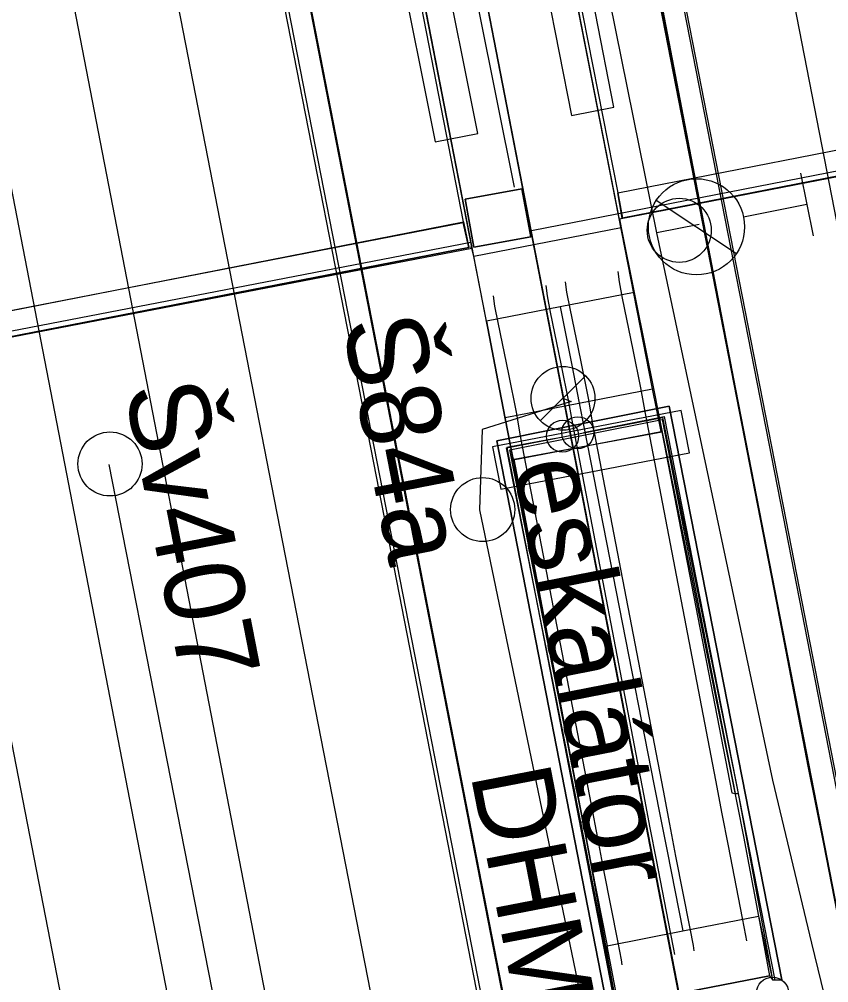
# Model space of a CAD drawing. Extents: x -545736 to -544888, y -1122892 to -1119128.
# Drawn here: x -545200.03 to -545187.41, y -1121808.48 to -1121793.44 of the extents above; entities that cross this region are included whole.
import ezdxf

# ---------------------------------------------------------------- set-up
doc = ezdxf.new("R2010")
doc.units = 0
for name, color, linetype in [('Podbarveni_Nastupiste', 7, 'Continuous'), ('Podbarveni_Zastreseni_Pozemni', 7, 'Continuous'), ('Vrstva 1 - Koleje', 7, 'Continuous'), ('Vrstva 13', 7, 'Continuous'), ('Vrstva 14_zastreseni a nastupiste', 7, 'Continuous'), ('Vrstva 16_plochy', 7, 'Continuous'), ('Vrstva 17_ploty - zabradli', 7, 'Continuous'), ('Vrstva 18_mosty', 7, 'Continuous'), ('Vrstva 23 - PHS - pozemni - schody - eskalatory', 7, 'Continuous'), ('Vrstva 29 - sdelzar', 7, 'Continuous'), ('Vrstva 30', 7, 'Continuous'), ('Vrstva 31', 7, 'Continuous'), ('Vrstva 33 - prvky sdelzar', 7, 'Continuous'), ('Vrstva 35', 7, 'Continuous'), ('Vrstva 4 - Teren - stezky - prechody - plochy', 7, 'Continuous'), ('Vrstva 41', 7, 'Continuous'), ('Vrstva 42', 7, 'Continuous'), ('Vrstva 43', 7, 'Continuous'), ('Vrstva 44', 7, 'Continuous'), ('Vrstva 47', 7, 'Continuous'), ('Vrstva 63', 7, 'Continuous')]:
    doc.layers.add(name, color=color, linetype=linetype)

msp = doc.modelspace()

# ---------------------------------------------------------------- linework, layer by layer
at = {"layer": 'Podbarveni_Nastupiste'}
for points in [[(-545217.368, -1121682.822), (-545215.446, -1121692.657), (-545213.545, -1121702.425), (-545211.641, -1121712.196), (-545209.721, -1121722.039), (-545207.816, -1121731.8), (-545205.906, -1121741.605), (-545203.994, -1121751.399), (-545202.093, -1121761.155), (-545200.179, -1121770.948), (-545198.277, -1121780.734), (-545196.359, -1121790.595), (-545195.979, -1121792.554), (-545194.455, -1121800.349), (-545192.535, -1121810.197), (-545190.626, -1121819.979), (-545188.728, -1121829.75), (-545186.804, -1121839.582), (-545184.9, -1121849.369), (-545182.993, -1121859.16)], [(-545176.664, -1121859.989), (-545178.574, -1121850.184), (-545180.481, -1121840.388), (-545182.39, -1121830.601), (-545184.299, -1121820.832), (-545186.202, -1121811.019), (-545188.114, -1121801.21), (-545190.028, -1121791.416), (-545191.936, -1121781.597), (-545194.23, -1121769.859), (-545195.758, -1121762.016), (-545197.67, -1121752.211), (-545199.585, -1121742.389), (-545201.492, -1121732.62), (-545203.329, -1121723.177), (-545205.298, -1121713.047), (-545207.216, -1121703.229), (-545209.127, -1121693.444), (-545211.033, -1121683.652)]]:
    msp.add_lwpolyline(points, dxfattribs=at)
at = {"layer": 'Podbarveni_Zastreseni_Pozemni'}
for points in [[(-545158.353, -1121955.704), (-545167.91, -1121906.688), (-545177.482, -1121857.6), (-545187.03, -1121808.63), (-545196.619, -1121759.457), (-545206.211, -1121710.262)], [(-545201.855, -1121760.601), (-545192.303, -1121809.6), (-545182.738, -1121858.66), (-545173.147, -1121907.858), (-545163.62, -1121956.724)]]:
    msp.add_lwpolyline(points, dxfattribs=at)
at = {"layer": 'Vrstva 1 - Koleje'}
for points in [[(-545219.01, -1121683.169), (-545217.101, -1121692.961), (-545215.17, -1121702.86), (-545213.27, -1121712.617), (-545211.361, -1121722.411), (-545209.465, -1121732.134), (-545207.557, -1121741.929), (-545205.641, -1121751.761), (-545203.736, -1121761.535), (-545201.841, -1121771.262), (-545199.933, -1121781.054), (-545197.636, -1121792.838), (-545196.098, -1121800.727), (-545194.176, -1121810.583), (-545192.282, -1121820.3), (-545190.374, -1121830.083), (-545188.448, -1121839.971), (-545186.548, -1121849.715), (-545184.635, -1121859.52)], [(-545209.393, -1121683.199), (-545207.488, -1121692.987), (-545205.563, -1121702.847), (-545203.658, -1121712.62), (-545201.742, -1121722.443), (-545199.842, -1121732.176), (-545197.931, -1121741.977), (-545196.019, -1121751.798), (-545194.112, -1121761.581), (-545192.212, -1121771.322), (-545190.282, -1121781.238), (-545188.375, -1121791.011), (-545186.47, -1121800.793), (-545184.553, -1121810.635), (-545182.663, -1121820.345), (-545180.739, -1121830.214), (-545178.835, -1121839.985), (-545176.93, -1121849.755), (-545175.02, -1121859.552)], [(-545223.305, -1121685.999), (-545221.784, -1121693.786), (-545219.807, -1121703.933), (-545217.963, -1121713.399), (-545216.049, -1121723.207), (-545214.151, -1121732.945), (-545212.247, -1121742.719), (-545210.325, -1121752.584), (-545208.439, -1121762.262), (-545206.519, -1121772.114), (-545204.606, -1121781.929), (-545202.699, -1121791.711), (-545200.792, -1121801.491), (-545198.893, -1121811.238), (-545196.998, -1121820.96), (-545195.061, -1121830.898), (-545193.152, -1121840.702), (-545191.231, -1121850.558), (-545189.315, -1121860.384)]]:
    msp.add_lwpolyline(points, dxfattribs=at)
at = {"layer": 'Vrstva 13'}
for points in [[(-545192.312, -1121796.062), (-545193.409, -1121790.59)], [(-545179.052, -1121794.207), (-545192.042, -1121796.744)], [(-545192.991, -1121796.926), (-545206.427, -1121799.524)]]:
    msp.add_lwpolyline(points, dxfattribs=at)
at = {"layer": 'Vrstva 14_zastreseni a nastupiste'}
for points in [[(-545217.368, -1121682.822), (-545215.446, -1121692.657), (-545213.545, -1121702.425), (-545211.641, -1121712.196), (-545209.721, -1121722.039), (-545207.816, -1121731.8), (-545205.906, -1121741.605), (-545203.994, -1121751.399), (-545202.093, -1121761.155), (-545200.179, -1121770.948), (-545198.277, -1121780.734), (-545196.359, -1121790.595), (-545195.979, -1121792.554), (-545194.455, -1121800.349), (-545192.535, -1121810.197), (-545190.626, -1121819.979), (-545188.728, -1121829.75), (-545186.804, -1121839.582), (-545184.9, -1121849.369), (-545182.993, -1121859.16)], [(-545217.421, -1121682.837), (-545215.499, -1121692.672), (-545213.598, -1121702.44), (-545211.694, -1121712.211), (-545209.774, -1121722.054), (-545207.869, -1121731.815), (-545205.959, -1121741.62), (-545204.047, -1121751.414), (-545202.146, -1121761.17), (-545200.232, -1121770.963), (-545198.33, -1121780.749), (-545196.412, -1121790.61), (-545196.032, -1121792.569), (-545194.508, -1121800.364), (-545192.588, -1121810.212), (-545190.679, -1121819.994), (-545188.781, -1121829.765), (-545186.857, -1121839.597), (-545184.953, -1121849.384), (-545183.046, -1121859.175)], [(-545176.664, -1121859.989), (-545178.574, -1121850.184), (-545180.481, -1121840.388), (-545182.39, -1121830.601), (-545184.299, -1121820.832), (-545186.202, -1121811.019), (-545188.114, -1121801.21), (-545190.028, -1121791.416), (-545191.936, -1121781.597), (-545194.23, -1121769.859), (-545195.758, -1121762.016), (-545197.67, -1121752.211), (-545199.585, -1121742.389), (-545201.492, -1121732.62), (-545203.329, -1121723.177), (-545205.298, -1121713.047), (-545207.216, -1121703.229), (-545209.127, -1121693.444), (-545211.033, -1121683.652)], [(-545176.62, -1121860.033), (-545178.53, -1121850.228), (-545180.437, -1121840.432), (-545182.346, -1121830.645), (-545184.255, -1121820.876), (-545186.158, -1121811.063), (-545188.07, -1121801.254), (-545189.984, -1121791.46), (-545191.892, -1121781.641), (-545194.186, -1121769.903), (-545195.714, -1121762.06), (-545197.626, -1121752.255), (-545199.541, -1121742.433), (-545201.448, -1121732.664), (-545203.285, -1121723.221), (-545205.254, -1121713.091), (-545207.172, -1121703.273), (-545209.083, -1121693.488), (-545210.989, -1121683.696)], [(-545206.211, -1121710.262), (-545196.619, -1121759.457), (-545187.03, -1121808.63), (-545177.482, -1121857.6), (-545167.91, -1121906.688), (-545158.353, -1121955.704)], [(-545158.353, -1121955.704), (-545167.959, -1121906.425), (-545177.532, -1121857.312), (-545187.064, -1121808.415), (-545196.682, -1121759.07), (-545206.197, -1121710.259)], [(-545211.47, -1121711.284), (-545201.855, -1121760.601), (-545192.303, -1121809.6), (-545182.738, -1121858.66), (-545173.147, -1121907.858), (-545163.62, -1121956.724), (-545163.626, -1121956.727), (-545173.205, -1121907.598), (-545182.779, -1121858.496), (-545192.361, -1121809.351), (-545201.935, -1121760.249), (-545211.481, -1121711.288)]]:
    msp.add_lwpolyline(points, dxfattribs=at)
for centre in [(-545191.559, -1121799.949), (-545191.323, -1121799.896), (-545188.284, -1121808.641)]:
    msp.add_circle(centre, 0.25, dxfattribs=at)
at = {"layer": 'Vrstva 16_plochy'}
for points in [[(-545217.368, -1121682.822), (-545215.446, -1121692.657), (-545213.545, -1121702.425), (-545211.641, -1121712.196), (-545209.721, -1121722.039), (-545207.816, -1121731.8), (-545205.906, -1121741.605), (-545203.994, -1121751.399), (-545202.093, -1121761.155), (-545200.179, -1121770.948), (-545198.277, -1121780.734), (-545196.359, -1121790.595), (-545195.979, -1121792.554), (-545194.455, -1121800.349), (-545192.535, -1121810.197), (-545190.626, -1121819.979), (-545188.728, -1121829.75), (-545186.804, -1121839.582), (-545184.9, -1121849.369), (-545182.993, -1121859.16)], [(-545176.664, -1121859.989), (-545178.574, -1121850.184), (-545180.481, -1121840.388), (-545182.39, -1121830.601), (-545184.299, -1121820.832), (-545186.202, -1121811.019), (-545188.114, -1121801.21), (-545190.028, -1121791.416), (-545191.936, -1121781.597), (-545194.23, -1121769.859), (-545195.758, -1121762.016), (-545197.67, -1121752.211), (-545199.585, -1121742.389), (-545201.492, -1121732.62), (-545203.329, -1121723.177), (-545205.298, -1121713.047), (-545207.216, -1121703.229), (-545209.127, -1121693.444), (-545211.033, -1121683.652)], [(-545188.332, -1121808.37), (-545188.287, -1121808.435), (-545188.139, -1121808.435), (-545189.897, -1121799.482), (-545192.587, -1121800.021), (-545190.842, -1121808.96), (-545190.704, -1121808.906), (-545190.687, -1121808.83), (-545188.332, -1121808.37)]]:
    msp.add_lwpolyline(points, dxfattribs=at)
at = {"layer": 'Vrstva 17_ploty - zabradli'}
for points in [[(-545188.685, -1121807.823), (-545188.7, -1121807.739), (-545188.752, -1121807.471), (-545188.971, -1121806.342), (-545189.068, -1121805.843), (-545189.167, -1121805.319), (-545190.267, -1121799.596), (-545190.337, -1121799.195), (-545190.457, -1121798.602), (-545190.623, -1121797.795), (-545190.673, -1121797.541), (-545190.693, -1121797.379)], [(-545189.809, -1121808.04), (-545189.823, -1121807.956), (-545189.875, -1121807.688), (-545190.094, -1121806.559), (-545190.191, -1121806.06), (-545190.29, -1121805.536), (-545191.39, -1121799.813), (-545191.46, -1121799.412), (-545191.58, -1121798.819), (-545191.746, -1121798.012), (-545191.796, -1121797.758), (-545191.816, -1121797.596)], [(-545189.506, -1121807.982), (-545189.52, -1121807.899), (-545189.572, -1121807.631), (-545189.791, -1121806.502), (-545189.888, -1121806.003), (-545189.987, -1121805.479), (-545191.087, -1121799.756), (-545191.157, -1121799.355), (-545191.277, -1121798.762), (-545191.443, -1121797.955), (-545191.493, -1121797.701), (-545191.513, -1121797.539)], [(-545190.629, -1121808.198), (-545190.643, -1121808.12), (-545190.695, -1121807.852), (-545190.914, -1121806.723), (-545191.011, -1121806.224), (-545191.11, -1121805.7), (-545192.21, -1121799.977), (-545192.28, -1121799.576), (-545192.4, -1121798.983), (-545192.566, -1121798.176), (-545192.616, -1121797.922), (-545192.636, -1121797.76)], [(-545191.233, -1121799.894), (-545189.977, -1121799.642), (-545188.25, -1121808.437)], [(-545191.67, -1121799.985), (-545192.431, -1121800.125), (-545190.731, -1121808.905)]]:
    msp.add_lwpolyline(points, dxfattribs=at)
at = {"layer": 'Vrstva 18_mosty'}
for points in [[(-545192.328, -1121800.319), (-545190.022, -1121799.876), (-545190.157, -1121799.212), (-545192.022, -1121789.664), (-545192.029, -1121789.613), (-545194.316, -1121790.08), (-545194.306, -1121790.118)], [(-545192.328, -1121800.319), (-545192.455, -1121799.656), (-545194.306, -1121790.118)], [(-545190.687, -1121808.83), (-545190.704, -1121808.906), (-545191.109, -1121806.663), (-545191.204, -1121806.164), (-545191.305, -1121805.64), (-545192.378, -1121800.073), (-545192.455, -1121799.674), (-545192.569, -1121799.08), (-545192.746, -1121798.156), (-545192.944, -1121797.145), (-545192.977, -1121797.022), (-545192.975, -1121797.001), (-545194.206, -1121790.672), (-545194.21, -1121790.664), (-545191.909, -1121790.222), (-545191.916, -1121790.223), (-545190.675, -1121796.567)], [(-545191.916, -1121790.223), (-545191.869, -1121790.221), (-545191.789, -1121790.613), (-545190.699, -1121796.152), (-545190.629, -1121796.547), (-545190.675, -1121796.567)], [(-545192.975, -1121797.001), (-545193.024, -1121797.005), (-545193.105, -1121796.607), (-545194.18, -1121791.072), (-545194.256, -1121790.684), (-545194.206, -1121790.672)], [(-545190.671, -1121796.557), (-545179.032, -1121794.298)], [(-545190.629, -1121796.547), (-545179.079, -1121794.292)], [(-545190.671, -1121796.557), (-545190.675, -1121796.567)], [(-545190.671, -1121796.557), (-545190.647, -1121796.696), (-545190.445, -1121797.706), (-545190.263, -1121798.614), (-545190.144, -1121799.207), (-545190.064, -1121799.603), (-545188.942, -1121805.177), (-545188.837, -1121805.699), (-545188.737, -1121806.197), (-545188.506, -1121807.439), (-545188.287, -1121808.435)], [(-545192.977, -1121797.022), (-545205.087, -1121799.354)], [(-545205.04, -1121799.345), (-545193.024, -1121797.005)], [(-545192.455, -1121799.656), (-545190.157, -1121799.212)], [(-545190.704, -1121808.906), (-545190.842, -1121808.96), (-545192.587, -1121800.021), (-545189.897, -1121799.482), (-545188.139, -1121808.435)], [(-545190.704, -1121808.906), (-545191.274, -1121805.975), (-545192.437, -1121800.134), (-545190.002, -1121799.658), (-545188.821, -1121805.525), (-545188.287, -1121808.435), (-545188.139, -1121808.435)], [(-545191.274, -1121805.975), (-545191.238, -1121805.963), (-545192.385, -1121800.164), (-545190.004, -1121799.688), (-545188.867, -1121805.523), (-545188.821, -1121805.525)], [(-545191.238, -1121805.963), (-545192.314, -1121800.309), (-545190.013, -1121799.88), (-545188.918, -1121805.515), (-545188.867, -1121805.523)], [(-545190.013, -1121799.88), (-545190.022, -1121799.876)], [(-545192.314, -1121800.309), (-545192.328, -1121800.319)]]:
    msp.add_lwpolyline(points, dxfattribs=at)
at = {"layer": 'Vrstva 23 - PHS - pozemni - schody - eskalatory'}
for points in [[(-545191.421, -1121794.946), (-545190.758, -1121794.816), (-545191.333, -1121791.876), (-545191.996, -1121792.006)], [(-545193.471, -1121792.287), (-545194.134, -1121792.419), (-545193.545, -1121795.357), (-545192.882, -1121795.224)], [(-545192.651, -1121800.114), (-545192.524, -1121800.778), (-545189.581, -1121800.212), (-545189.709, -1121799.548)]]:
    msp.add_lwpolyline(points, close=True, dxfattribs=at)
for points in [[(-545190.647, -1121796.696), (-545192.944, -1121797.145)], [(-545190.647, -1121796.696), (-545190.445, -1121797.706), (-545191.596, -1121797.931), (-545192.746, -1121798.156), (-545192.944, -1121797.145)], [(-545190.445, -1121797.706), (-545190.263, -1121798.614), (-545190.144, -1121799.207), (-545190.064, -1121799.603), (-545188.942, -1121805.177), (-545188.837, -1121805.699), (-545188.737, -1121806.197), (-545188.506, -1121807.439)], [(-545191.596, -1121797.931), (-545191.417, -1121798.84), (-545191.3, -1121799.433), (-545191.223, -1121799.829), (-545190.129, -1121805.406), (-545190.026, -1121805.929), (-545189.928, -1121806.427), (-545189.684, -1121807.67)], [(-545192.746, -1121798.156), (-545192.569, -1121799.08), (-545192.455, -1121799.674), (-545192.378, -1121800.073), (-545191.305, -1121805.64), (-545191.204, -1121806.164), (-545191.109, -1121806.663), (-545190.862, -1121807.9)], [(-545188.332, -1121808.37), (-545190.687, -1121808.83), (-545190.862, -1121807.9), (-545189.684, -1121807.67), (-545188.506, -1121807.439), (-545188.332, -1121808.37)]]:
    msp.add_lwpolyline(points, dxfattribs=at)
at = {"layer": 'Vrstva 29 - sdelzar'}
for points in [[(-545161.23, -1121954.22), (-545161.32, -1121954.32), (-545161.96, -1121950.99), (-545166.14, -1121929.44), (-545169.48, -1121912.2), (-545172.98, -1121894.15), (-545175.25, -1121882.41), (-545176.61, -1121875.48), (-545179.9, -1121858.78), (-545183.24, -1121841.76), (-545186.55, -1121824.95), (-545189.52, -1121809.83), (-545189.53, -1121809.79), (-545193.1, -1121791.33), (-545195.35, -1121779.72), (-545196.68, -1121772.84), (-545200.02, -1121755.61), (-545203.25, -1121738.95), (-545206.49, -1121722.18), (-545208.31, -1121712.8), (-545208.32, -1121712.72)], [(-545176.77, -1121874.7), (-545188.39, -1121815.6), (-545196.86, -1121771.93)]]:
    msp.add_lwpolyline(points, dxfattribs=at)
at = {"layer": 'Vrstva 30'}
msp.add_lwpolyline([(-545196.67, -1121771.94), (-545196.89, -1121771.78), (-545189.47, -1121810.09), (-545188.62, -1121809.93)], dxfattribs=at)
at = {"layer": 'Vrstva 31'}
msp.add_lwpolyline([(-545170.61, -1121902.505), (-545169.83, -1121902.32), (-545169.8, -1121901.51), (-545169.011, -1121900.695), (-545173.164, -1121879.068), (-545180.354, -1121842.406), (-545185.455, -1121816.369), (-545187.73, -1121805.097), (-545192.507, -1121780.186), (-545194.432, -1121775.331), (-545195.406, -1121775.086)], dxfattribs=at)
at = {"layer": 'Vrstva 35'}
for points in [[(-545190.699, -1121796.152), (-545179.16, -1121793.896)], [(-545190.699, -1121796.152), (-545179.161, -1121793.897)], [(-545179.161, -1121793.897), (-545179.079, -1121794.292), (-545190.629, -1121796.547), (-545190.699, -1121796.152)], [(-545190.626, -1121796.548), (-545179.079, -1121794.292)], [(-545190.699, -1121796.152), (-545190.699, -1121796.152), (-545190.626, -1121796.548), (-545190.629, -1121796.547)], [(-545205.121, -1121798.953), (-545193.108, -1121796.616)], [(-545205.118, -1121798.959), (-545193.105, -1121796.607)], [(-545193.105, -1121796.607), (-545193.024, -1121797.005), (-545205.04, -1121799.345), (-545205.118, -1121798.959)], [(-545193.024, -1121797.005), (-545193.024, -1121797.006), (-545193.108, -1121796.616), (-545193.105, -1121796.607)], [(-545205.04, -1121799.348), (-545193.024, -1121797.006)]]:
    msp.add_lwpolyline(points, dxfattribs=at)
at = {"layer": 'Vrstva 4 - Teren - stezky - prechody - plochy'}
for points in [[(-545157.45, -1122022.175), (-545154.783, -1122021.634), (-545154.868, -1122020.873), (-545158.409, -1122002.766), (-545161.985, -1121984.181), (-545167.947, -1121953.502), (-545173.012, -1121927.482), (-545183.259, -1121874.859), (-545192.216, -1121829.241), (-545202.384, -1121776.657), (-545211.092, -1121732.141), (-545220.696, -1121682.724), (-545230.205, -1121633.983), (-545237.607, -1121595.717), (-545239.248, -1121596.014)], [(-545157.45, -1122022.175), (-545157.217, -1122021.677), (-545160.795, -1122002.888), (-545164.002, -1121984.847), (-545169.404, -1121955.723), (-545174.573, -1121927.833), (-545184.757, -1121874.943), (-545193.65, -1121829.68), (-545203.839, -1121777.07), (-545212.63, -1121732.332), (-545221.738, -1121685.421), (-545231.797, -1121634.381), (-545239.248, -1121596.014)], [(-545217.421, -1121682.837), (-545215.499, -1121692.672), (-545213.598, -1121702.44), (-545211.694, -1121712.211), (-545209.774, -1121722.054), (-545207.869, -1121731.815), (-545205.959, -1121741.62), (-545204.047, -1121751.414), (-545202.146, -1121761.17), (-545200.232, -1121770.963), (-545198.33, -1121780.749), (-545196.412, -1121790.61), (-545196.032, -1121792.569), (-545194.508, -1121800.364), (-545192.588, -1121810.212), (-545190.679, -1121819.994), (-545188.781, -1121829.765), (-545186.857, -1121839.597), (-545184.953, -1121849.384), (-545183.046, -1121859.175)], [(-545176.62, -1121860.033), (-545178.53, -1121850.228), (-545180.437, -1121840.432), (-545182.346, -1121830.645), (-545184.255, -1121820.876), (-545186.158, -1121811.063), (-545188.07, -1121801.254), (-545189.984, -1121791.46), (-545191.892, -1121781.641), (-545194.186, -1121769.903), (-545195.714, -1121762.06), (-545197.626, -1121752.255), (-545199.541, -1121742.433), (-545201.448, -1121732.664), (-545203.285, -1121723.221), (-545205.254, -1121713.091), (-545207.172, -1121703.273), (-545209.083, -1121693.488), (-545210.989, -1121683.696)]]:
    msp.add_lwpolyline(points, dxfattribs=at)
at = {"layer": 'Vrstva 41'}
for p, q in [((-545187.847, -1121795.844), (-545187.649, -1121796.824)), ((-545190.098, -1121796.267), (-545188.847, -1121797.098)), ((-545187.748, -1121796.334), (-545188.736, -1121796.533))]:
    msp.add_line(p, q, dxfattribs=at)
for centre, radius in [((-545189.471, -1121796.682), 0.75), ((-545189.74, -1121796.737), 0.5)]:
    msp.add_circle(centre, radius, dxfattribs=at)
at = {"layer": 'Vrstva 42'}
msp.add_line((-545189.431, -1121796.646), (-545190.092, -1121796.779), dxfattribs=at)
for points in [[(-545187.672, -1121807.861), (-545188.279, -1121805.317), (-545190.092, -1121796.779), (-545192.19, -1121786.382), (-545191.911, -1121784.451), (-545193.213, -1121778.689), (-545193.775, -1121776.175), (-545195.394, -1121768.95), (-545201.581, -1121737.891), (-545201.754, -1121737.117)], [(-545203.534, -1121918.02), (-545198.847, -1121917.36), (-545185.567, -1121915.086), (-545176.946, -1121913.531), (-545167.572, -1121911.811), (-545169.511, -1121901.523), (-545169.772, -1121900.147), (-545173.971, -1121879.393), (-545174.091, -1121878.805), (-545174.196, -1121878.05), (-545174.272, -1121877.624), (-545174.386, -1121877.061), (-545179.482, -1121851.396), (-545181.349, -1121842.633), (-545184.905, -1121824.51), (-545186.898, -1121813.243), (-545186.931, -1121810.892), (-545187.672, -1121807.861)]]:
    msp.add_lwpolyline(points, dxfattribs=at)
at = {"layer": 'Vrstva 43'}
msp.add_line((-545191.907, -1121799.71), (-545191.202, -1121799.006), dxfattribs=at)
for centre, radius in [((-545191.554, -1121799.359), 0.498), ((-545198.62, -1121800.383), 0.5), ((-545192.806, -1121801.095), 0.5)]:
    msp.add_circle(centre, radius, dxfattribs=at)
at = {"layer": 'Vrstva 44'}
for points in [[(-545191.555, -1121799.358), (-545191.426, -1121799.41), (-545192.815, -1121799.846), (-545192.854, -1121801.099), (-545190.114, -1121814.291), (-545189.96, -1121814.512), (-545189.86, -1121814.806), (-545186.511, -1121831.238), (-545183.538, -1121845.823), (-545183.49, -1121846.087)], [(-545198.638, -1121800.39), (-545189.536, -1121846.787), (-545189.41, -1121847.096)]]:
    msp.add_lwpolyline(points, dxfattribs=at)
at = {"layer": 'Vrstva 47'}
for points in [[(-545192.944, -1121797), (-545193.081, -1121796.253), (-545192.195, -1121796.09), (-545192.057, -1121796.838), (-545192.944, -1121797)], [(-545193.081, -1121796.253), (-545192.944, -1121797), (-545192.057, -1121796.838), (-545192.195, -1121796.09), (-545193.081, -1121796.253)], [(-545192.195, -1121796.09), (-545192.195, -1121796.09)], [(-545193.081, -1121796.253), (-545193.081, -1121796.253)], [(-545192.057, -1121796.838), (-545192.057, -1121796.838)], [(-545192.944, -1121797), (-545192.944, -1121797)]]:
    msp.add_lwpolyline(points, dxfattribs=at)

# ---------------------------------------------------------------- texts
at = {"layer": 'Vrstva 33 - prvky sdelzar'}
msp.add_text('DHM4', height=1.25, rotation=280.9585, dxfattribs=at).set_placement((-545192.999, -1121805.22))
at = {"layer": 'Vrstva 43'}
for s, rotation, p in [('Š84a', 281.0281, (-545195, -1121798.173)), ('Šv407', 281.0323, (-545198.396, -1121799.205))]:
    msp.add_text(s, height=1.25, rotation=rotation, dxfattribs=at).set_placement(p)
at = {"layer": 'Vrstva 63'}
msp.add_text('eskalátor', height=1.25, rotation=281.0984, dxfattribs=at).set_placement((-545192.337, -1121800.393))

doc.saveas('drawing.dxf')
